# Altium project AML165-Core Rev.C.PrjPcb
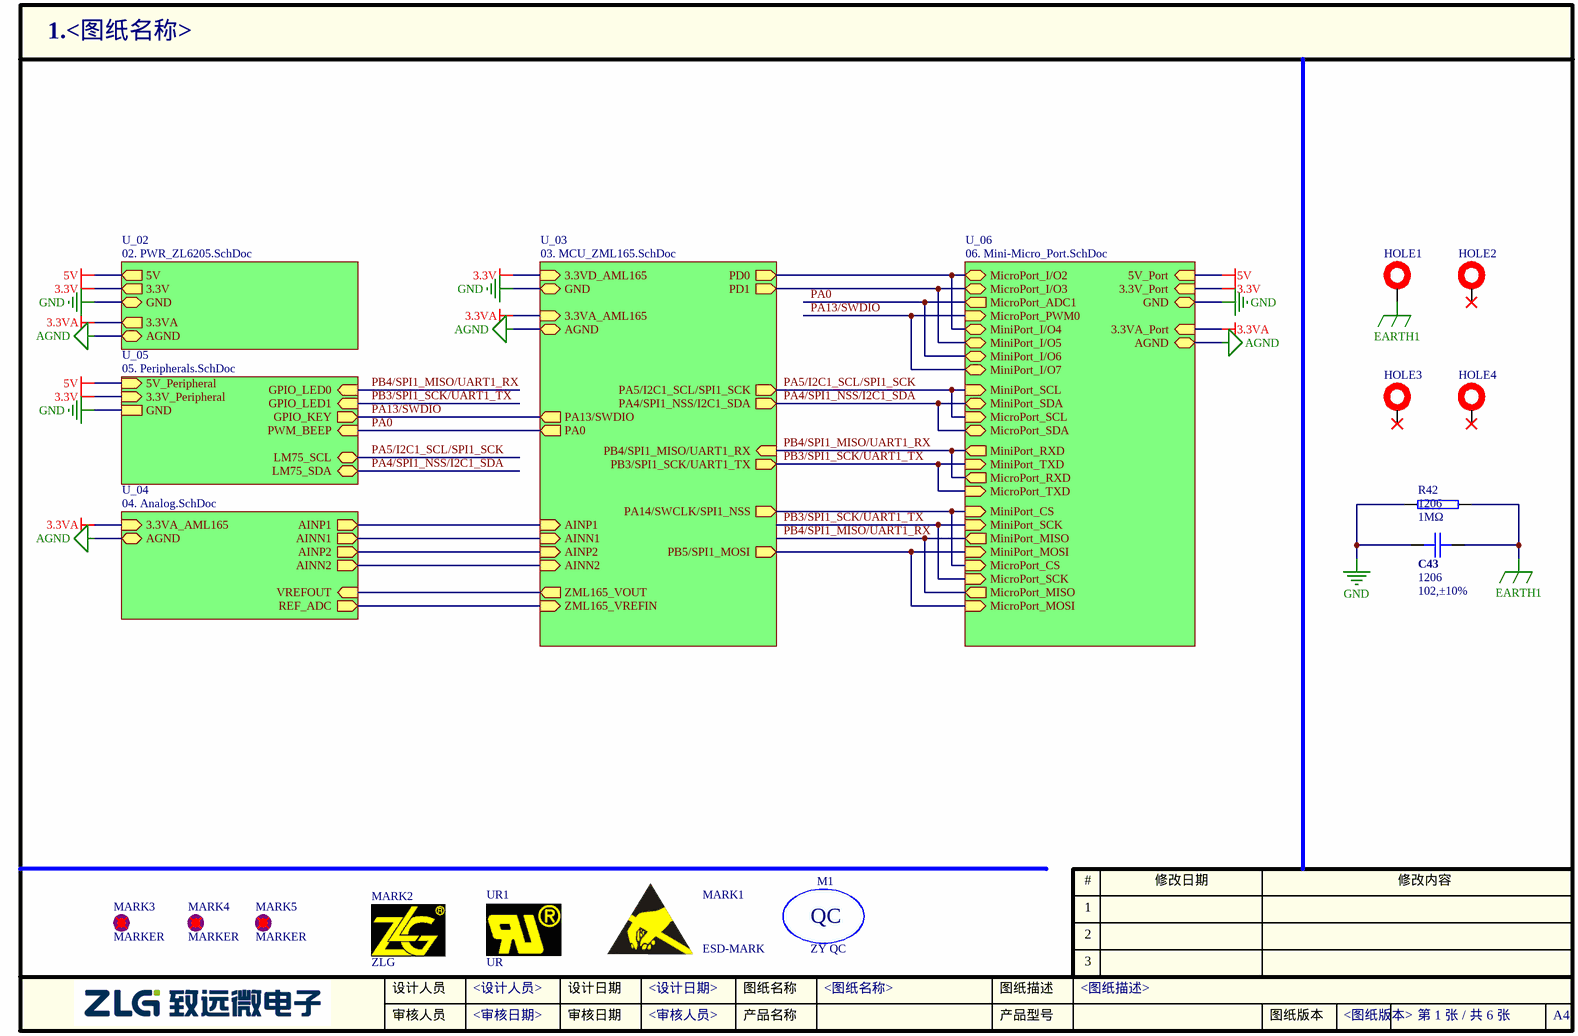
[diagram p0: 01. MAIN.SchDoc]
6 sheets, 150 parts. Net scope: hierarchical (ports join the sheet entries above them; power ports are global).
Board file: AML165-Core Rev.C.PcbDoc
Sheets:
  01. MAIN.SchDoc
    U_04 = 04. Analog.SchDoc
    U_02 = 02. PWR_ZL6205.SchDoc
    U_05 = 05. Peripherals.SchDoc
    U_06 = 06. Mini-Micro_Port.SchDoc
    U_03 = 03. MCU_ZML165.SchDoc

## Sheet 01. MAIN.SchDoc
size A4; CheckedBy: <审核日期>; Author: <设计人员>; CompanyName: 广州立功科技股份有限公司; DocumentNumber: 1; SheetNumber: 1; SheetTotal: 6; PageSetup: Record=PageOptions|CenterHorizontal=True|CenterVertical=True|PrintScale=1.00|XCorrection=1.00|YCorrection=1.00|PrintKind=0|BorderSize=5000000|LeftOffset=0|BottomOffset=0|Orientation=2|PaperLength=1000|PaperWidth=1000|Scale=100|PaperSource=7|PrintQuality=600|MediaType=1|DitherType=10|PaperKind=A4|PrintScaleMode=1; DesignDate: <设计日期>; CheckDate: <审核人员>; SheetName: <图纸名称>; SheetVersion: <图纸版本>; SheetDescription: <图纸描述>

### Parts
C43  封装: 1206  [1206C]  (hidden comment: 102,±10%)
HOLE1  (no value)  [HOLE-3.2]  (no BOM)
HOLE2  (no value)  [HOLE-3.2]  (no BOM)
HOLE3  (no value)  [HOLE-3.2]  (no BOM)
HOLE4  (no value)  [HOLE-3.2]  (no BOM)
M1  ZY QC  [ZY_QC]  (no BOM)
MARK1  ESD-MARK  [ZY_ESD-7]
MARK2  ZLG  [ZLG0.7]  (no BOM)
MARK3  MARKER  [MARKER-C-0.8M]  (no BOM)
MARK4  MARKER  [MARKER-C-0.8M]  (no BOM)
MARK5  MARKER  [MARKER-C-0.8M]  (no BOM)
R42  封装: 1206  [1206R]  (hidden comment: 1MΩ)
UR1  UR  [ZY_UR-3X2]

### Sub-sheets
U_02 = 02. PWR_ZL6205.SchDoc: 5V (out), 3.3V (out), 3.3VA (out), GND (bidir), AGND (bidir)
U_03 = 03. MCU_ZML165.SchDoc: 3.3VD_AML165 (in), GND (bidir), 3.3VA_AML165 (in), AGND (bidir), AINP1 (in), AINN1 (in), AINP2 (in), AINN2 (in), ZML165_VREFIN (in), ZML165_VOUT (out), PB3/SPI1_SCK/UART1_TX (out), PB4/SPI1_MISO/UART1_RX (in), PB5/SPI1_MOSI (out), PA14/SWCLK/SPI1_NSS (out), PA5/I2C1_SCL/SPI1_SCK (out), PA4/SPI1_NSS/I2C1_SDA (out), PA13/SWDIO (out), PA0 (out), PD0 (out), PD1 (out)
U_04 = 04. Analog.SchDoc: 3.3VA_AML165 (in), AGND (bidir), AINP1 (out), AINN1 (out), AINP2 (out), AINN2 (out), REF_ADC (out), VREFOUT (in)
U_05 = 05. Peripherals.SchDoc: GPIO_LED0 (in), GPIO_LED1 (in), PWM_BEEP (in), GPIO_KEY (out), LM75_SCL (bidir), LM75_SDA (bidir), 5V_Peripheral (in), 3.3V_Peripheral (in), GND
U_06 = 06. Mini-Micro_Port.SchDoc: MiniPort_SDA (bidir), MiniPort_SCL (in), MiniPort_MOSI (in), MiniPort_SCK (in), MiniPort_MISO (out), MiniPort_CS (in), MiniPort_TXD (in), MiniPort_RXD (out), MicroPort_RXD (out), MicroPort_TXD (in), MicroPort_SCK (in), MicroPort_MISO (out), MicroPort_MOSI (in), MicroPort_CS (in), MicroPort_SDA (bidir), MicroPort_SCL (in), 3.3V_Port (in), GND (bidir), 3.3VA_Port (in), AGND (bidir), 5V_Port (in), MicroPort_ADC1 (out), MicroPort_PWM0 (in), MiniPort_I/O7 (bidir), MiniPort_I/O6 (bidir), MiniPort_I/O5 (bidir), MiniPort_I/O4 (bidir), MicroPort_I/O2 (bidir), MicroPort_I/O3 (bidir)

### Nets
3.3V: sheet U_02/3.3V, sheet U_05/3.3V_Peripheral, sheet U_06/3.3V_Port, sheet U_03/3.3VD_AML165
3.3VA: sheet U_04/3.3VA_AML165, sheet U_02/3.3VA, sheet U_06/3.3VA_Port, sheet U_03/3.3VA_AML165
5V: sheet U_02/5V, sheet U_05/5V_Peripheral, sheet U_06/5V_Port
AGND: sheet U_04/AGND, sheet U_02/AGND, sheet U_06/AGND, sheet U_03/AGND
EARTH1: C43.2 HOLE1.1 R42.2
GND: C43.1 R42.1 ; sheet U_02/GND, sheet U_05/GND, sheet U_06/GND, sheet U_03/GND
AINN1: sheet U_04/AINN1, sheet U_03/AINN1
AINN2: sheet U_04/AINN2, sheet U_03/AINN2
AINP1: sheet U_04/AINP1, sheet U_03/AINP1
AINP2: sheet U_04/AINP2, sheet U_03/AINP2
MicroPort_CS: sheet U_06/MiniPort_CS, sheet U_06/MicroPort_CS, sheet U_03/PA14/SWCLK/SPI1_NSS
MicroPort_I/O2: sheet U_06/MiniPort_I/O4, sheet U_06/MicroPort_I/O2, sheet U_03/PD0
MicroPort_I/O3: sheet U_06/MiniPort_I/O5, sheet U_06/MicroPort_I/O3, sheet U_03/PD1
MicroPort_MOSI: sheet U_06/MiniPort_MOSI, sheet U_06/MicroPort_MOSI, sheet U_03/PB5/SPI1_MOSI
PA0: sheet U_05/PWM_BEEP, sheet U_06/MicroPort_ADC1, sheet U_06/MiniPort_I/O6, sheet U_03/PA0  [project net MicroPort_ADC1]
PA4/SPI1_NSS/I2C1_SDA: sheet U_05/LM75_SDA, sheet U_06/MiniPort_SDA, sheet U_06/MicroPort_SDA, sheet U_03/PA4/SPI1_NSS/I2C1_SDA  [project net LM75_SDA]
PA5/I2C1_SCL/SPI1_SCK: sheet U_05/LM75_SCL, sheet U_06/MiniPort_SCL, sheet U_06/MicroPort_SCL, sheet U_03/PA5/I2C1_SCL/SPI1_SCK  [project net LM75_SCL]
PA13/SWDIO: sheet U_05/GPIO_KEY, sheet U_06/MicroPort_PWM0, sheet U_06/MiniPort_I/O7, sheet U_03/PA13/SWDIO  [project net GPIO_KEY]
PB3/SPI1_SCK/UART1_TX: sheet U_05/GPIO_LED1, sheet U_06/MiniPort_SCK, sheet U_06/MiniPort_TXD, sheet U_06/MicroPort_TXD, sheet U_06/MicroPort_SCK, sheet U_03/PB3/SPI1_SCK/UART1_TX  [project net GPIO_LED1]
PB4/SPI1_MISO/UART1_RX: sheet U_05/GPIO_LED0, sheet U_06/MiniPort_MISO, sheet U_06/MiniPort_RXD, sheet U_06/MicroPort_RXD, sheet U_06/MicroPort_MISO, sheet U_03/PB4/SPI1_MISO/UART1_RX  [project net GPIO_LED0]
REF_ADC: sheet U_04/REF_ADC, sheet U_03/ZML165_VREFIN
VREFOUT: sheet U_04/VREFOUT, sheet U_03/ZML165_VOUT

Not connected (* = marked no-connect by the designer): HOLE2 1*; HOLE3 1*; HOLE4 1*; MARK3 0*; MARK4 0*; MARK5 0*

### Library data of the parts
C43 = 1.02.03.0003: 102,±10%,2KV,X7R,1206,*,RoHS; 名称: 电容; 设备封装名称: C1206_102_X7R_2KV_10%; 贴片和直插: SMT
HOLE1-HOLE4 = HOLE - 不上螺丝
R42 = 1.01.03.0019: 名称: 电阻; 规格型号: 1MΩ,1206,RoHS; 设备封装名称: R1206_1M; 贴片和直插: SMT; 现有库存: 12252

## Sheet 04. Analog.SchDoc
size A4; CheckedBy: <审核日期>; Author: <设计人员>; CompanyName: 广州立功科技股份有限公司; DocumentNumber: 4; SheetNumber: 4; SheetTotal: 6; PageSetup: Record=PageOptions|CenterHorizontal=True|CenterVertical=True|PrintScale=1.00|XCorrection=1.00|YCorrection=1.00|PrintKind=0|BorderSize=5000000|LeftOffset=0|BottomOffset=0|Orientation=2|PaperLength=1000|PaperWidth=1000|Scale=100|PaperSource=7|PrintQuality=600|MediaType=1|DitherType=10|PaperKind=A4|PrintScaleMode=1; DesignDate: <设计日期>; CheckDate: <审核人员>; SheetName: <图纸名称>; SheetVersion: <图纸版本>; SheetDescription: <图纸描述>
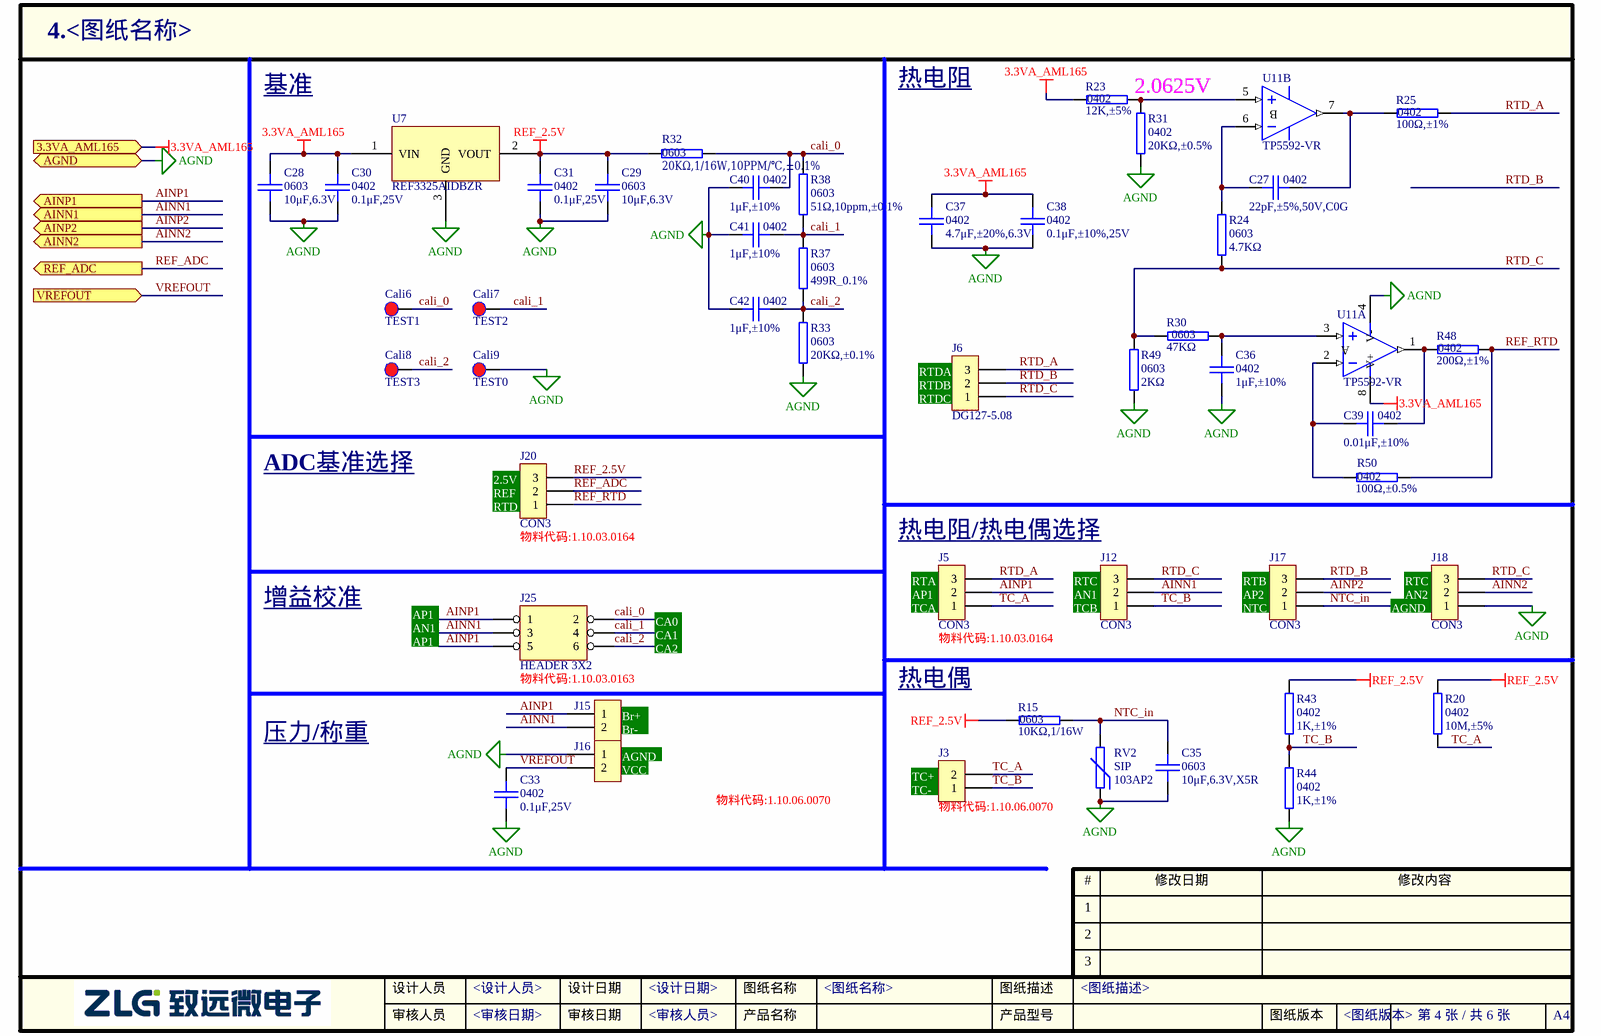
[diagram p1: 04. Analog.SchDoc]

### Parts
C27  封装: 0402  型号: 22pF,±5%,50V,C0G  [0402C]  (hidden comment: 22pF,±5%)
C28  封装: 0603  [0603C]  (hidden comment: 10μF,6.3V)
C29  封装: 0603  [0603C]  (hidden comment: 10μF,6.3V)
C30  封装: 0402  型号: 0.1μF,25V  [0402C]  (hidden comment: GCM155R71E104KE02D,0.1μF)
C31  封装: 0402  型号: 0.1μF,25V  [0402C]  (hidden comment: GCM155R71E104KE02D,0.1μF)
C33  封装: 0402  型号: 0.1μF,25V  [0402C]  (hidden comment: GCM155R71E104KE02D,0.1μF)
C35  封装: 0603  型号: 10μF,6.3V,X5R  [0603C]  (hidden comment: 10μF)
C36  封装: 0402  [0402C]  (hidden comment: 1μF,±10%)
C37  封装: 0402  型号: 4.7μF,±20%,6.3V  [0402C]  (hidden comment: 4.7μF)
C38  封装: 0402  型号: 0.1μF,±10%,25V  [0402C]  (hidden comment: 0.1μF)
C39  封装: 0402  [0402C]  (hidden comment: 0.01μF,±10%)
C40  封装: 0402  [0402C]  (hidden comment: 1μF,±10%)
C41  封装: 0402  [0402C]  (hidden comment: 1μF,±10%)
C42  封装: 0402  [0402C]  (hidden comment: 1μF,±10%)
Cali6  TEST1  [PAD-25/40]  (no BOM)
Cali7  TEST2  [PAD-25/40]  (no BOM)
Cali8  TEST3  [PAD-25/40]  (no BOM)
Cali9  TEST0  [PAD-25/40]  (no BOM)
J3  DG127-5.08-02P-14-00AH,180°  [CON508P1016L810W110D15S-2DIP]  (value not drawn)
J5  CON3  [SIP-3-2.54]
J6  DG127-5.08  [CON508P1524L810W110D15S-3DIP]
J12  CON3  [SIP-3-2.54]
J15  DG127-5.08-02P-14-00AH,180°  [CON508P1016L810W110D15S-2DIP]  (value not drawn)
J16  DG127-5.08-02P-14-00AH,180°  [CON508P1016L810W110D15S-2DIP]  (value not drawn)
J17  CON3  [SIP-3-2.54]
J18  CON3  [SIP-3-2.54]
J20  CON3  [SIP-3-2.54]
J25  HEADER 3X2  [IDC-6-2.54]
R15  封装: 0603  [0603R]  (hidden comment: 10KΩ,1/16W)
R20  封装: 0402  [0402R]  (hidden comment: 10M,±5%)
R23  封装: 0402  [0402R]  (hidden comment: 12K,±5%)
R24  封装: 0603  [0603R]  (hidden comment: 4.7KΩ)
R25  封装: 0402  [0402R]  (hidden comment: 100Ω,±1%)
R30  封装: 0603  [0603R]  (hidden comment: 47KΩ)
R31  封装: 0402  [0402R]  (hidden comment: 20KΩ,±0.5%)
R32  封装: 0603  型号: 20KΩ,1/16W,10PPM/℃,±0.1%  [0603R]  (hidden comment: 20KΩ,1/16W)
R33  封装: 0603  型号: 20KΩ,±0.1%  [0603R]  (hidden comment: 20KΩ,1/16W)
R37  封装: 0603  设备封装名称: 499R_0.1%  [0603R]  (hidden comment: 499Ω)
R38  封装: 0603  型号: 51Ω,10ppm,±0.1%  [0603R]  (hidden comment: 51Ω,10ppm)
R43  封装: 0402  [0402R]  (hidden comment: 1K,±1%)
R44  封装: 0402  [0402R]  (hidden comment: 1K,±1%)
R48  封装: 0402  [0402R]  (hidden comment: 200Ω,±1%)
R49  封装: 0603  [0603R]  (hidden comment: 2KΩ)
R50  封装: 0402  [0402R]  (hidden comment: 100Ω,±0.5%)
RV2  封装: SIP  [RESRR254W35L380T260H850P]  (hidden comment: 103AP2)
U7  REF3325AIDBZR  [SOT-23]
U11  TP5592-VR  [SOP65P490X120-8N]  (parts A,B of 2)

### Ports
3.3VA_AML165 (in), AGND (bidir), AINN1 (out), AINN2 (out), AINP1 (out), AINP2 (out), REF_ADC (out), VREFOUT (in)

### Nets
3.3VA_AML165: C28.2 C30.2 C37.1 C38.1 R23.1 U7.1(VIN) U11.8(V+) ; port 3.3VA_AML165  [project net 3.3VA]
AGND: C28.1 C29.1 C30.1 C31.1 C33.1 C35.1 C36.2 C37.2 C38.2 C40.1 C41.1 C42.1 Cali9.1 J16.1 J18.1 R31.1 R33.2 R44.2 R49.2 RV2.1 U7.3(GND) U11.4(V-) ; port AGND
REF_2.5V: C29.2 C31.2 J20.3 R15.2 R20.1 R32.2 R43.2 U7.2(VOUT)
AINN1: J12.2 J15.2 J25.3 ; port AINN1
AINN2: J18.2 ; port AINN2
AINP1: J5.2 J15.1 J25.1 J25.5 ; port AINP1
AINP2: J17.2 ; port AINP2
cali_0: C40.2 Cali6.1 J25.2 R32.1 R38.1
cali_1: C41.2 Cali7.1 J25.4 R37.2 R38.2
cali_2: C42.2 Cali8.1 J25.6 R33.1 R37.1
NTC_in: C35.2 J17.1 R15.1 RV2.2
REF_ADC: J20.2 ; port REF_ADC
REF_RTD: J20.1 R48.2 R50.1
RTD_A: J5.3 J6.3 R25.1
RTD_B: J6.2 J17.3
RTD_C: J6.1 J12.3 J18.3 R24.2 R30.1 R49.1
TC_A: J3.2 J5.1 R20.2
TC_B: J3.1 J12.1 R43.1 R44.1
VREFOUT: C33.2 J16.2 ; port VREFOUT
NetC27_1: C27.1 R24.1 U11.6(IN-)
NetC27_2: C27.2 R25.2 U11.7(OUT)
NetC36_1: C36.1 R30.2 U11.3(IN+)
NetC39_1: C39.1 R50.2 U11.2(IN-)
NetC39_2: C39.2 R48.1 U11.1(OUT)
NetR23_2: R23.2 R31.2 U11.5(IN+)

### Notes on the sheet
- 基准
- 热电阻
- 2.0625V
- (near J6) RTDA
  RTDB
  RTDC
- ADC基准选择
- (near J20) 2.5V
- (near J20) REF
- (near J20) RTD
- (near J20) 物料代码:1.10.03.0164
- (near J5) 热电阻/热电偶选择
- (near J5) RTA
- (near J12) RTC
- (near J17) RTB
- (near J18) RTC
- 增益校准
- AP1
- AN1
- CA0
- CA1
- CA2
- (near J5) TCA
- (near J5) AP1
- (near J5) 物料代码:1.10.03.0164
- (near J12) TCB
- (near J12) AN1
- (near J17) NTC
- (near J17) AP2
- (near J18) AGND
- (near J18) AN2
- 物料代码:1.10.03.0163
- Br+
- 热电偶
- 压力/称重
- Br-
- VCC
- AGND
- (near J3) TC+
- (near J3) TC-
- (near J16) 物料代码:1.10.06.0070
- (near J3) 物料代码:1.10.06.0070

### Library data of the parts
C27 = 1.02.17.0036: GRM1555C1H220JA01D,22pF,±5%,50V,C0G,0402,muRata,RoHS; 名称: 电容; 设备封装名称: C0402_22PF_NPO_50V_5%; 贴片和直插: SMT; 器件优选方案: 正常状态，可以选用
C28 C29 C35 = 1.02.01.0065: 10μF,6.3V,X5R,GRM188R60J106M****,0603,Murata,RoHS; 名称: 电容; 贴片和直插: SMT; 器件优选方案: 正常状态，可以选用
C30 C31 C33 C38 = 1.02.17.0118: GCM155R71E104KE02D,0.1μF,±10%,25V,X7R,0402,muRata,RoHS; 名称: 电容; 贴片和直插: SMT; PCB备注: 161012yjh; 器件优选方案: 正常状态，可以选用
C36 C40-C42 = 1.02.17.0092: GRM155R61C105KA12D,1μF,±10% ,16V,X5R,0402,muRata,RoHS; 名称: 电容; 贴片和直插: SMT; PCB备注: 无数据手册，依据采购部提供的信息添加的封装。; 器件优选方案: 正常状态，可以选用
C37 = 1.02.17.0073: GRM155R60J475ME87D,4.7μF,±20%,6.3V,X5R,0402,muRata,RoHS; 名称: 电容; 贴片和直插: SMT; 器件优选方案: 正常状态，可以选用
C39 = 1.02.17.0019: GRM155R71H103KA88D,0.01μF,±10%,50V,X7R,0402,muRata,RoHS; 名称: 电容; 设备封装名称: C0402_0.01uF_X7R_50V_10%; 贴片和直插: SMT; 器件优选方案: 正常状态，可以选用
Cali6-Cali9 = TEST-DOT
J3 J15 J16 = 1.10.06.0070: DG127-5.08-02P-14-00AH,180°,绿色,DEGSON,RoHS; 名称: 端子; 贴片和直插: THT; PCB备注: xhm-lq-wyy-150126 yyf改名称180925; 器件优选方案: 正常状态，可以选用
J5 J12 J17 J18 J20 = CON3: Connector
J6 = 19.04.00251: DG127-5.08-03P-14-00AH,180°,绿色,THT; 名称: 端子; PCB备注: 180925 yyf
R15 = 1.01.01.0192: 10KΩ,1/16W,10PPM/℃,±0.1%,0603,Viking,RoHS; 名称: 电阻; 设备封装名称: R0603_10K_0.1%; 型号: 10KΩ,±0.1%; 贴片和直插: SMT; 器件优选方案: 临时/偏门物料/不主推物料，谨慎选用
R20 = 1.01.17.0005: 10M,±5%,0402,RALEC,RoHS; 名称: 电阻; 设备封装名称: R0402_10M; 贴片和直插: SMT; 器件优选方案: 正常状态，可以选用
R23 = 1.01.17.0035: 12K,±5%,0402,RALEC,RoHS; 名称: 电阻; 设备封装名称: R0402_12K; 贴片和直插: SMT; 器件优选方案: 正常状态，可以选用
R24 = 1.01.01.0045: 4.7KΩ,0603,*,RoHS; 名称: 电阻; 设备封装名称: R0603_4.7K; 厂商: Ralec; 贴片和直插: SMT; 器件优选方案: 正常状态，可以选用
R25 = 1.01.17.0029: 100Ω,±1%,0402,RALEC,RoHS; 名称: 电阻; 设备封装名称: R0402_100R_1%; 贴片和直插: SMT; 器件优选方案: 正常状态，可以选用
R30 = 1.01.01.0060: 47KΩ,0603,*,RoHS; 名称: 电阻; 设备封装名称: R0603_47K; 厂商: Ralec; 贴片和直插: SMT; 器件优选方案: 正常状态，可以选用
R31 = 1.01.17.0053: 20KΩ,±0.5%,0402,RoHS; 名称: 电阻; 设备封装名称: R0402_20K_0.5%; 厂商: Ralec; 贴片和直插: SMT; 器件优选方案: 正常状态，可以选用
R32 R33 = 1.01.01.0207: 20KΩ,1/16W,10PPM/℃,±0.1%,0603,Viking,RoHS; 名称: 电阻; 贴片和直插: SMT; 器件优选方案: 临时/偏门物料/不主推物料，谨慎选用
R37 = 1.01.01.0155: 499Ω,RN731JTTD,4990B10,0603,KOA,RoHS; 名称: 电阻; 贴片和直插: SMT; 器件优选方案: 临时/偏门物料/不主推物料，谨慎选用
R38 = 1.01.01.0215: 51Ω,10ppm,±0.1%,AR03BTB0510,0603,Viking,RoHS; 名称: 电阻; 贴片和直插: SMT; 器件优选方案: 临时/偏门物料/不主推物料，谨慎选用
R43 R44 = 1.01.17.0016: 1K,±1%,0402,RALEC,RoHS; 名称: 电阻; 设备封装名称: R0402_1K_1%; 贴片和直插: SMT; 器件优选方案: 正常状态，可以选用
R48 = 1.01.17.0073: 200Ω,±1%,0402,RoHS; 名称: 电阻; 设备封装名称: R0402_200R_1%; 厂商: Ralec; 贴片和直插: SMT; 器件优选方案: 正常状态，可以选用
R49 = 1.01.01.0157: 2KΩ,RN731JTTD,2001B10,0603,KOA,RoHS; 名称: 电阻; 设备封装名称: R0603_2K_0.1%; 贴片和直插: SMT; 器件优选方案: 临时/偏门物料/不主推物料，谨慎选用
R50 = 1.01.17.0052: 100Ω,±0.5%,0402,RoHS; 名称: 电阻; 设备封装名称: R0402_100R_0.5%; 厂商: Ralec; 贴片和直插: SMT; 器件优选方案: 正常状态，可以选用
RV2 = 1.01.14.0020: 103AP2,SIP,semitec,RoHS; 名称: 热敏电阻(临时); 贴片和直插: THT; PCB备注: 171205CZY; 器件优选方案: 临时/偏门物料/不主推物料，谨慎选用
U7 = 1.05.10.0334: REF3325AIDBZR,SOT-23,TI; 名称: 集成电路; 设备封装名称: SOT-23_REF3325AIDBZR; 贴片和直插: SMT; 器件优选方案: 量产物料,优先选用
U11 = 1.05.20.0102: TP5592-VR,MSOP-8,3PEAK,RoHS; 名称: 集成电路(临时); 贴片和直插: SMT; PCB备注: 170810lmd; 器件优选方案: 临时/偏门物料/不主推物料，谨慎选用

## Sheet 02. PWR_ZL6205.SchDoc
size A4; CheckedBy: <审核日期>; Author: <设计人员>; CompanyName: 广州立功科技股份有限公司; DocumentNumber: 2; SheetNumber: 2; SheetTotal: 6; PageSetup: Record=PageOptions|CenterHorizontal=True|CenterVertical=True|PrintScale=1.00|XCorrection=1.00|YCorrection=1.00|PrintKind=0|BorderSize=5000000|LeftOffset=0|BottomOffset=0|Orientation=2|PaperLength=1000|PaperWidth=1000|Scale=100|PaperSource=7|PrintQuality=600|MediaType=1|DitherType=10|PaperKind=A4|PrintScaleMode=1; DesignDate: <设计日期>; CheckDate: <审核人员>; SheetName: <图纸名称>; SheetVersion: <图纸版本>; SheetDescription: <图纸描述>
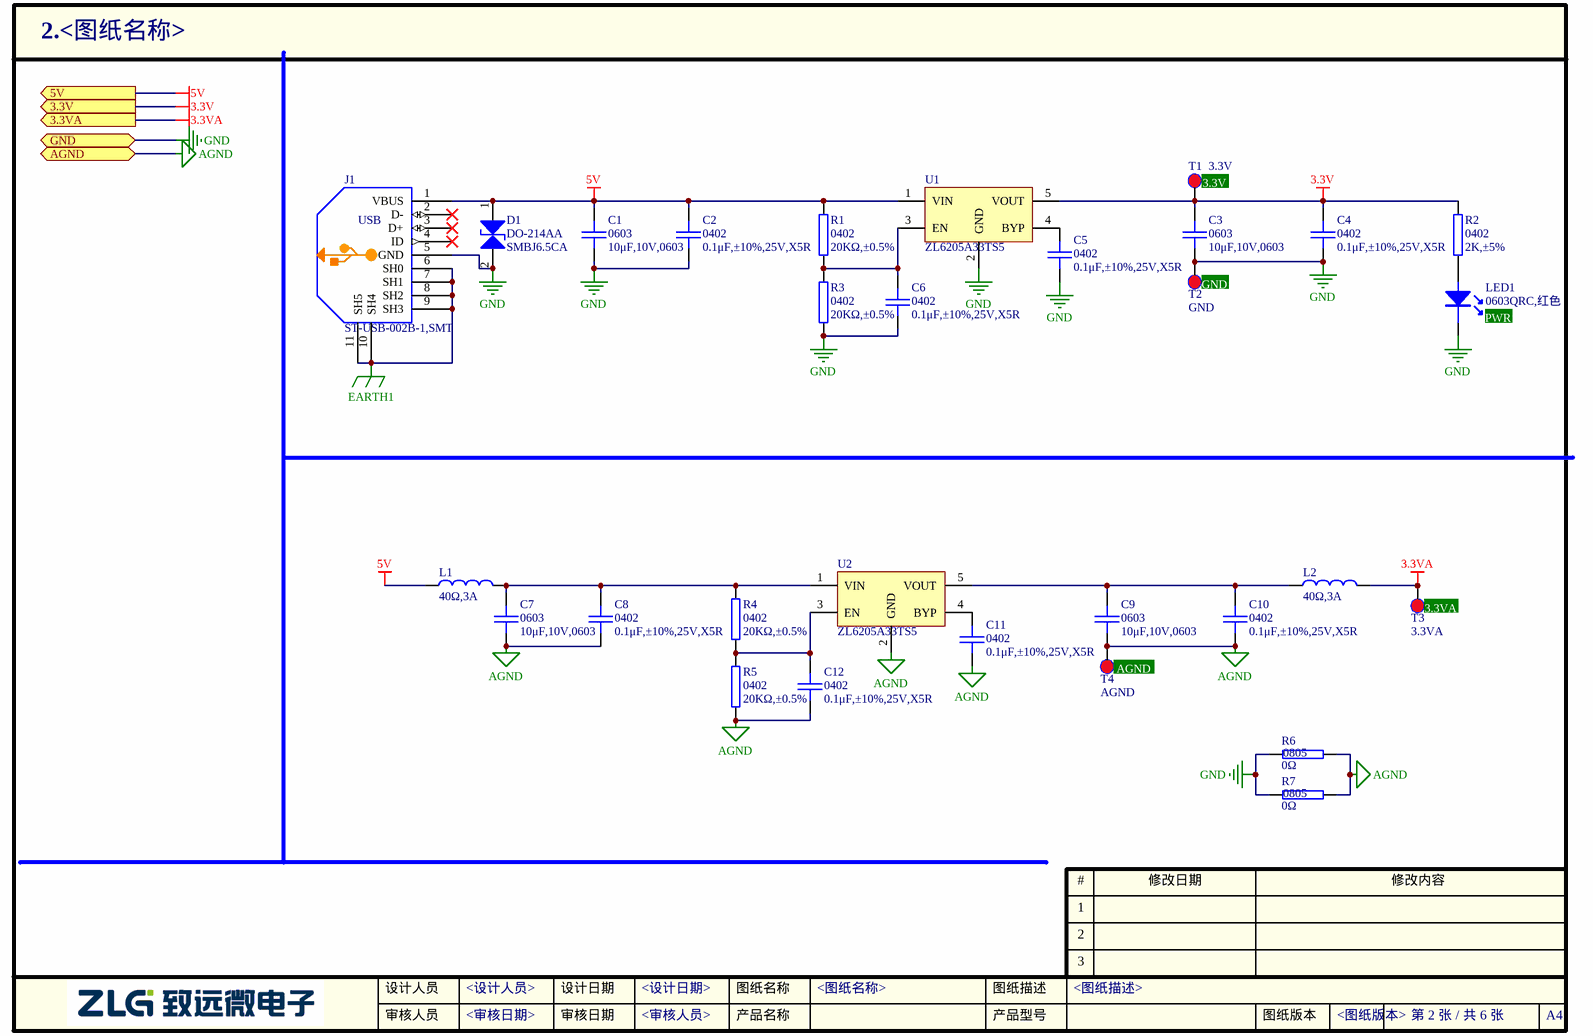
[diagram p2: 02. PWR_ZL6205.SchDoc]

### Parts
C1  封装: 0603  [0603C]  (hidden comment: 10μF,10V,0603)
C2  封装: 0402  型号: 0.1μF,±10%,25V,X5R  [0402C]  (hidden comment: 0.1μF,±10%)
C3  封装: 0603  [0603C]  (hidden comment: 10μF,10V,0603)
C4  封装: 0402  型号: 0.1μF,±10%,25V,X5R  [0402C]  (hidden comment: 0.1μF,±10%)
C5  封装: 0402  型号: 0.1μF,±10%,25V,X5R  [0402C]  (hidden comment: 0.1μF,±10%)
C6  封装: 0402  型号: 0.1μF,±10%,25V,X5R  [0402C]  (hidden comment: 0.1μF,±10%)
C7  封装: 0603  [0603C]  (hidden comment: 10μF,10V,0603)
C8  封装: 0402  型号: 0.1μF,±10%,25V,X5R  [0402C]  (hidden comment: 0.1μF,±10%)
C9  封装: 0603  [0603C]  (hidden comment: 10μF,10V,0603)
C10  封装: 0402  型号: 0.1μF,±10%,25V,X5R  [0402C]  (hidden comment: 0.1μF,±10%)
C11  封装: 0402  型号: 0.1μF,±10%,25V,X5R  [0402C]  (hidden comment: 0.1μF,±10%)
C12  封装: 0402  型号: 0.1μF,±10%,25V,X5R  [0402C]  (hidden comment: 0.1μF,±10%)
D1  封装: DO-214AA  [SOD-1812]  (hidden comment: SMBJ6.5CA)
J1  ST-USB-002B-1,SMT  [MICROUSB-ST-USB-002B-1]
L1  40Ω,3A  [0603L]
L2  40Ω,3A  [0603L]
LED1  0603QRC,红色  [LED-0603]
R1  封装: 0402  [0402R]  (hidden comment: 20KΩ,±0.5%)
R2  封装: 0402  [0402R]  (hidden comment: 2K,±5%)
R3  封装: 0402  [0402R]  (hidden comment: 20KΩ,±0.5%)
R4  封装: 0402  [0402R]  (hidden comment: 20KΩ,±0.5%)
R5  封装: 0402  [0402R]  (hidden comment: 20KΩ,±0.5%)
R6  封装: 0805  [0805R]  (hidden comment: 0Ω)
R7  封装: 0805  [0805R]  (hidden comment: 0Ω)
T1  3.3V  [PAD-25/40]  (no BOM)
T2  GND  [PAD-25/40]  (no BOM)
T3  3.3VA  [PAD-25/40]  (no BOM)
T4  AGND  [PAD-25/40]  (no BOM)
U1  ZL6205A33TS5  [SOT-23-5]
U2  ZL6205A33TS5  [SOT-23-5]

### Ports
3.3V (out), 3.3VA (out), 5V (out), AGND (bidir), GND (bidir)

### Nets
3.3V: C3.1 C4.2 R2.2 T1.1 U1.5(VOUT) ; port 3.3V
3.3VA: L2.2 T3.1 ; port 3.3VA
5V: C1.1 C2.2 D1.1(A) J1.1(VBUS) L1.1 R1.1 U1.1(VIN) ; port 5V
AGND: C7.2 C8.1 C9.2 C10.1 C11.1 C12.1 R5.2 R6.2 R7.2 T4.1 U2.2(GND) ; port AGND
EARTH1: J1.6(SH0) J1.7(SH1) J1.8(SH2) J1.9(SH3) J1.10(SH4) J1.11(SH5)
GND: C1.2 C2.1 C3.2 C4.1 C5.1 C6.1 D1.2(K) J1.5(GND) LED1.2 R3.2 R6.1 R7.1 T2.1 U1.2(GND) ; port GND
NetC5_2: C5.2 U1.4(BYP)
NetC6_2: C6.2 R1.2 R3.1 U1.3(EN)
NetC7_1: C7.1 C8.2 L1.2 R4.1 U2.1(VIN)
NetC9_1: C9.1 C10.2 L2.1 U2.5(VOUT)
NetC11_2: C11.2 U2.4(BYP)
NetC12_2: C12.2 R4.2 R5.1 U2.3(EN)
NetLED1_1: LED1.1 R2.1

Not connected (* = marked no-connect by the designer): J1 2(D-)* 3(D+)* 4(ID)*

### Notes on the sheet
- (near T1) 3.3V
- (near T2) GND
- (near LED1) PWR
- (near T3) 3.3VA
- (near T4) AGND

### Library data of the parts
C1 C3 C7 C9 = 02.01.00456: GRM188D71A106MA73D,0603,Murata,10μF,X7T,±20%,10V; 名称: 电容; 贴片和直插: SMT; PCB备注: 190613hcj; 器件优选方案: 通用物料
C2 C4-C6 C8 C10-C12 = 1.02.17.0020: GRM155R61E104KA87D,0.1μF,±10%,25V,X5R,0402,muRata,RoHS; 名称: 电容; 设备封装名称: C0402_0.1uF_X5R_25V_10%; 贴片和直插: SMT; 器件优选方案: 正常状态，可以选用
D1 = 1.04.03.0003: SMBJ6.5CA,DO-214AA,君耀,RoHS; 名称: TVS瞬态抑制二极管; 设备封装名称: DO-214AA_SMBJ6.5CA; 贴片和直插: SMT; 器件优选方案: 正常状态，可以选用
J1 = 20.02.00033: ST-USB-002B-1,SMT,SUNGTECH,MicroUSB-A; 名称: 连接器; PCB备注: 190710lmd; 器件优选方案: 通用物料
L1 L2 = 1.03.03.0011: 40Ω,3A,DCR35mΩ,BH03Y314S-40R,SMD,0603,丰晶,RoHS; 名称: 磁珠; 封装: 0603; 贴片和直插: SMT; 器件优选方案: 正常状态，可以选用
LED1 = 1.04.05.0008: 0603QRC,红色,0603,创光,RoHS; 名称: 发光二极管; 封装: 0603; 设备封装名称: LED0603-RED; 贴片和直插: SMT; 器件优选方案: 正常状态，可以选用
R1 R3-R5 = 1.01.17.0053: as R31 on sheet 04. Analog
R2 = 1.01.17.0032: 2K,±5%,0402,RALEC,RoHS; 名称: 电阻; 设备封装名称: R0402_2K; 贴片和直插: SMT; 器件优选方案: 正常状态，可以选用
R6 R7 = 1.01.02.0001: 0Ω,0805,*,RoHS; 名称: 电阻; 设备封装名称: R0805_0R; 厂商: Ralec; 贴片和直插: SMT; 器件优选方案: 正常状态，可以选用
T1-T4 = TEST-DOT
U1 U2 = 08.09.03069: ZL6205A33TS5,SOT-23-5,ZLG; 名称: 集成电路; 贴片和直插: SMT; PCB备注: 190806hcj; 器件优选方案: 待导入物料

## Sheet 05. Peripherals.SchDoc
size A4; CheckedBy: <审核日期>; Author: <设计人员>; CompanyName: 广州立功科技股份有限公司; DocumentNumber: 5; SheetNumber: 5; SheetTotal: 6; PageSetup: Record=PageOptions|CenterHorizontal=True|CenterVertical=True|PrintScale=1.00|XCorrection=1.00|YCorrection=1.00|PrintKind=0|BorderSize=5000000|LeftOffset=0|BottomOffset=0|Orientation=2|PaperLength=1000|PaperWidth=1000|Scale=100|PaperSource=7|PrintQuality=600|MediaType=1|DitherType=10|PaperKind=A4|PrintScaleMode=1; DesignDate: <设计日期>; CheckDate: <审核人员>; SheetName: <图纸名称>; SheetVersion: <图纸版本>; SheetDescription: <图纸描述>
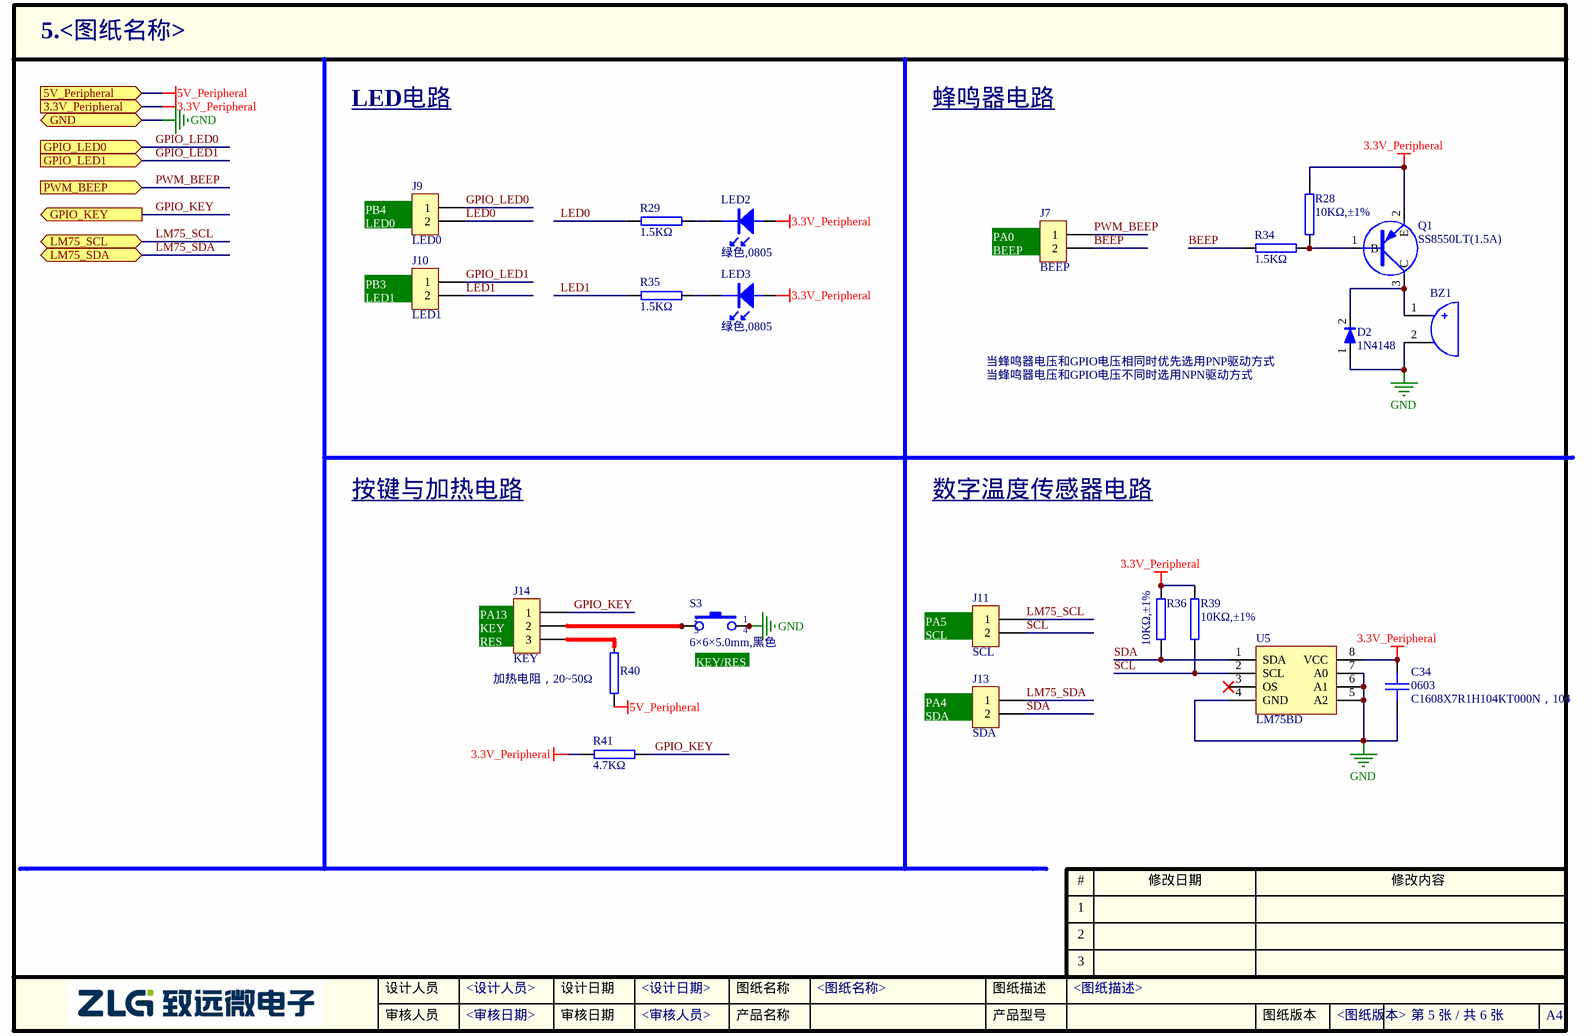
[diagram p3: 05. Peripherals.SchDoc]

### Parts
BZ1  BUZZER2  [BUZZ-4/9]  (value not drawn)
C34  封装: 0603  [0603C]  (hidden comment: C1608X7R1H104KT000N，104)
D2  value 1N4148  [SOD-323]  (hidden comment: DIODE1)
J7  BEEP  [SIP-2-2.54]
J9  LED0  [SIP-2-2.54]
J10  LED1  [SIP-2-2.54]
J11  SCL  [SIP-2-2.54]
J13  SDA  [SIP-2-2.54]
J14  KEY  [SIP-3-2.54]
LED2  value 绿色,0805  [LED-0805]  (hidden comment: LED0)
LED3  value 绿色,0805  [LED-0805]  (hidden comment: LED1)
Q1  value SS8550LT(1.5A)  [SOT-23]  (hidden comment: PNP-1)
R28  10KΩ,±1%  [0603R]
R29  1.5KΩ  [0603R]
R34  1.5KΩ  [0603R]
R35  1.5KΩ  [0603R]
R36  10KΩ,±1%  [0603R]
R39  10KΩ,±1%  [0603R]
R40  20Ω,±5%  [RESAD1778W80L1450D430P]  (value not drawn)
R41  4.7KΩ  [0603R]
S3  value 6×6×5.0mm,黑色  [KEY-6S]  (hidden comment: KEY/RES)
U5  value LM75BD  [SOIC127P600X175-8N]  (hidden comment: LM75B)

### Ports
3.3V_Peripheral (in), 5V_Peripheral (in), GND, GPIO_KEY (out), GPIO_LED0 (in), GPIO_LED1 (in), LM75_SCL (bidir), LM75_SDA (bidir), PWM_BEEP (in)

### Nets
3.3V_Peripheral: C34.1 LED2.1 LED3.1 Q1.2(E) R28.2 R36.2 R39.2 R41.2 U5.8(VCC) ; port 3.3V_Peripheral  [project net 3.3V]
5V_Peripheral: R40.1 ; port 5V_Peripheral  [project net 5V]
GND: BZ1.2(B) C34.2 D2.1 S3.1 S3.4 U5.4(GND) U5.5(A2) U5.6(A1) U5.7(A0) ; port GND
BEEP: J7.2 R34.1
GPIO_KEY: J14.1 R41.1 ; port GPIO_KEY
GPIO_LED0: J9.1 ; port GPIO_LED0
GPIO_LED1: J10.1 ; port GPIO_LED1
LED0: J9.2 R29.2
LED1: J10.2 R35.2
LM75_SCL: J11.1 ; port LM75_SCL
LM75_SDA: J13.1 ; port LM75_SDA
PWM_BEEP: J7.1 ; port PWM_BEEP  [project net MicroPort_ADC1]
SCL: J11.2 R39.1 U5.2(SCL)
SDA: J13.2 R36.1 U5.1(SDA)
NetBZ1_1: BZ1.1(A) D2.2 Q1.3(C)
NetJ14_2: J14.2 S3.2 S3.3
NetJ14_3: J14.3 R40.2
NetLED2_2: LED2.2 R29.1
NetLED3_2: LED3.2 R35.1
NetQ1_1: Q1.1(B) R28.1 R34.2

Not connected (* = marked no-connect by the designer): U5 3(OS)*

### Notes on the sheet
- LED电路
- 蜂鸣器电路
- (near J9) LED0
- (near J9) PB4
- (near J7) PA0
- (near J7) BEEP
- (near J10) LED1
- (near J10) PB3
- 当蜂鸣器电压和GPIO电压不同时选用NPN驱动方式
- 当蜂鸣器电压和GPIO电压相同时优先选用PNP驱动方式
- 按键与加热电路
- 数字温度传感器电路
- (near J14) RES
- (near J14) KEY
- (near J14) PA13
- (near J11) PA5
- (near J11) SCL
- 加热电阻，20~50Ω
- (near S3) KEY/RES
- (near J13) PA4
- (near J13) SDA

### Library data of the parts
BZ1 = 1.06.09.0016: Buzzer有极性; Value: AS-905I-LF,无源; 名称: 讯响器; 厂商: 常州笠翔; 型号: AS-905I-LF,无源,Ф9×4.8mm; 贴片和直插: THT; PCB备注: Flq-Shcj-Twrj-150113; 器件优选方案: 量产物料,优先选用
C34 = 1.02.01.0072: C1608X7R1H104KT000N，104，±10%，50V，X7R,TDK,0603,RoHS; 名称: 电容; 贴片和直插: SMT; PCB备注: 151110lmd; 器件优选方案: 正常状态，可以选用
D2 = 1.04.07.0027: 1N4148,SOD-323,RoHS; 名称: 二极管; 设备封装名称: SOD-323_1N4148; 贴片和直插: SMT
J7 J9-J11 J13 = CON2: Connector; 物料代码: 1.10.03.0164
J14 = CON3: Connector; 物料代码: 1.10.03.0164
LED2 LED3 = 1.04.05.0002: 绿色,0805,0805,RoHS; 名称: 发光二极管; 封装: 0805; 设备封装名称: LED0805-GREEN; 贴片和直插: SMT; 器件优选方案: 样品物料,谨慎选用
Q1 = 1.04.09.0002: PNP Transistor; 名称: 三极管; 设备封装名称: SOT-23_SS8550LT; 厂商: 江苏长电; 贴片和直插: SMT
R28 = 1.01.01.0052: 10KΩ,±1%,0603,*,RoHS; 名称: 电阻; 封装: 0603; 设备封装名称: R0603_10K_1%; 厂商: Ralec; 贴片和直插: SMT
R29 R35 = 1.01.01.0037: 1.5KΩ,0603,*,RoHS; 名称: 电阻; 封装: 0603; 设备封装名称: R0603_1.5K; 厂商: Ralec; 贴片和直插: SMT; 器件优选方案: 正常状态，可以选用
R34 = 1.01.01.0037: 1.5KΩ,0603,*,RoHS; 名称: 电阻; 封装: 0603; 设备封装名称: R0603_1.5K; 厂商: Ralec; 贴片和直插: SMT; 器件优选方案: 状态正常
R36 R39 = 1.01.01.0052: 10KΩ,±1%,0603,*,RoHS; 名称: 电阻; 封装: 0603; 设备封装名称: R0603_10K_1%; 厂商: Ralec; 贴片和直插: SMT; 器件优选方案: 正常状态，可以选用
R40 = 1.01.10.0003: 20Ω,±5%,2W,Ф5.5×16mm,RoHS; 名称: 电阻; 贴片和直插: THT
R41 = 1.01.01.0045: 4.7KΩ,0603,*,RoHS; 名称: 电阻; 封装: 0603; 设备封装名称: R0603_4.7K; 厂商: Ralec; 贴片和直插: SMT; 器件优选方案: 正常状态，可以选用
S3 = 1.09.01.0003: 6×6×5.0mm,黑色,SMD,,*; 名称: 轻触按键; 贴片和直插: SMT
U5 = 1.05.10.0602: LM75BD,SO-9,NXP,RoHS; 名称: IC; 封装: SO-8; 贴片和直插: SMT; 器件优选方案: 样品物料,谨慎选用

## Sheet 06. Mini-Micro_Port.SchDoc
size A4; CheckedBy: <审核日期>; Author: <设计人员>; CompanyName: 广州立功科技股份有限公司; DocumentNumber: 6; SheetNumber: 6; SheetTotal: 6; PageSetup: Record=PageOptions|CenterHorizontal=True|CenterVertical=True|PrintScale=1.00|XCorrection=1.00|YCorrection=1.00|PrintKind=0|BorderSize=5000000|LeftOffset=0|BottomOffset=0|Orientation=2|PaperLength=1000|PaperWidth=1000|Scale=100|PaperSource=7|PrintQuality=600|MediaType=1|DitherType=10|PaperKind=A4|PrintScaleMode=1; DesignDate: <设计日期>; CheckDate: <审核人员>; SheetName: <图纸名称>; SheetVersion: <图纸版本>; SheetDescription: <图纸描述>
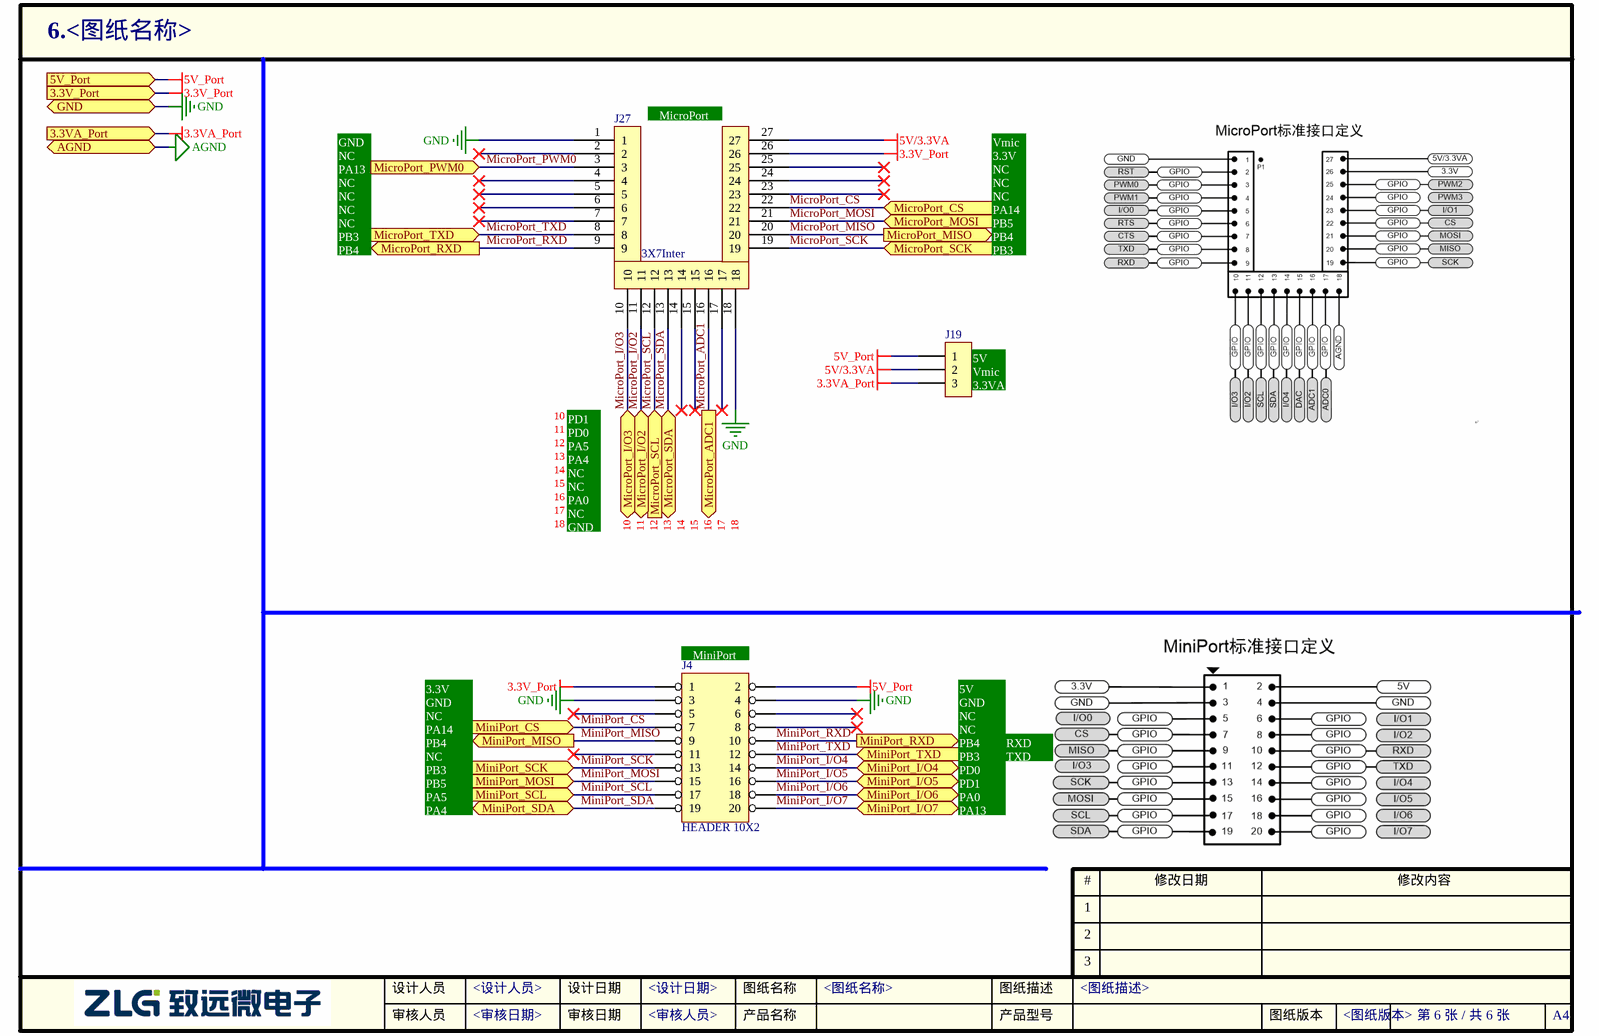
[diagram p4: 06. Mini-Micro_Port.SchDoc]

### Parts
J4  HEADER 10X2  [IDC-20-2.54-R90]
J19  (no value)  [SIP-3-2.54]
J27  3X7Inter  [SIP-27 2.54C]

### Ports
3.3V_Port (in), 3.3VA_Port (in), 5V_Port (in), AGND (bidir), GND (bidir), MicroPort_ADC1 (out), MicroPort_CS (in), MicroPort_I/O2 (bidir), MicroPort_I/O3 (bidir), MicroPort_MISO (out), MicroPort_MOSI (in), MicroPort_PWM0 (in), MicroPort_RXD (out), MicroPort_SCK (in), MicroPort_SCL (in), MicroPort_SDA (bidir), MicroPort_TXD (in), MiniPort_CS (in), MiniPort_I/O4 (bidir), MiniPort_I/O5 (bidir), MiniPort_I/O6 (bidir), MiniPort_I/O7 (bidir), MiniPort_MISO (out), MiniPort_MOSI (in), MiniPort_RXD (out), MiniPort_SCK (in), MiniPort_SCL (in), MiniPort_SDA (bidir), MiniPort_TXD (in)

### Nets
3.3V_Port: J4.1 J27.26 ; port 3.3V_Port  [project net 3.3V]
3.3VA_Port: J19.3 ; port 3.3VA_Port  [project net 3.3VA]
5V/3.3VA: J19.2 J27.27
5V_Port: J4.2 J19.1 ; port 5V_Port  [project net 5V]
GND: J4.3 J4.4 J27.1 J27.18 ; port GND
MicroPort_ADC1: J4.18 J27.16 ; port MicroPort_ADC1, port MiniPort_I/O6  [also labelled MiniPort_I/O6]
MicroPort_CS: J4.7 J27.22 ; port MiniPort_CS, port MicroPort_CS  [also labelled MiniPort_CS]
MicroPort_I/O2: J4.14 J27.11 ; port MiniPort_I/O4, port MicroPort_I/O2  [also labelled MiniPort_I/O4]
MicroPort_I/O3: J4.16 J27.10 ; port MiniPort_I/O5, port MicroPort_I/O3  [also labelled MiniPort_I/O5]
MicroPort_MISO: J4.9 J4.10 J27.9 J27.20 ; port MiniPort_MISO, port MiniPort_RXD, port MicroPort_RXD, port MicroPort_MISO  [also labelled MicroPort_RXD, MiniPort_MISO, MiniPort_RXD]  [project net GPIO_LED0]
MicroPort_MOSI: J4.15 J27.21 ; port MiniPort_MOSI, port MicroPort_MOSI  [also labelled MiniPort_MOSI]
MicroPort_PWM0: J4.20 J27.3 ; port MicroPort_PWM0, port MiniPort_I/O7  [also labelled MiniPort_I/O7]  [project net GPIO_KEY]
MicroPort_SCK: J4.12 J4.13 J27.8 J27.19 ; port MiniPort_SCK, port MiniPort_TXD, port MicroPort_TXD, port MicroPort_SCK  [also labelled MicroPort_TXD, MiniPort_SCK, MiniPort_TXD]  [project net GPIO_LED1]
MicroPort_SCL: J4.17 J27.12 ; port MiniPort_SCL, port MicroPort_SCL  [also labelled MiniPort_SCL]  [project net LM75_SCL]
MicroPort_SDA: J4.19 J27.13 ; port MiniPort_SDA, port MicroPort_SDA  [also labelled MiniPort_SDA]  [project net LM75_SDA]

Not connected (* = marked no-connect by the designer): J4 5* 6* 8* 11*; J27 2* 4* 5* 6* 7* 14* 15* 17* 23* 24* 25*

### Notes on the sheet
- (near J27) MicroPort
- NC
- PA13
- GND
- 3.3V
- Vmic
- PB3
- PB4
- PA14
- PB5
- (near J19) 5V
- (near J19) Vmic
  3.3VA
- 10
- 11
- 12
- PA5
- PD1
- PD0
- 13
- 14
- 15
- 16
- 17
- PA0
- PA4
- 18
- (near J4) MiniPort
- 5V
- RXD
- TXD

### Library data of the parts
J4 = HEADER 10X2: 物料代码: 1.10.03.0016
J19 = CON3: Connector; 物料代码: 1.10.03.0164
J27 = 3X7Inter: 物料代码: 1.10.11.0074

## Sheet 03. MCU_ZML165.SchDoc
size A4; CheckedBy: <审核日期>; Author: <设计人员>; CompanyName: 广州立功科技股份有限公司; DocumentNumber: 3; SheetNumber: 3; SheetTotal: 6; PageSetup: Record=PageOptions|CenterHorizontal=True|CenterVertical=True|PrintScale=1.00|XCorrection=1.00|YCorrection=1.00|PrintKind=0|BorderSize=5000000|LeftOffset=0|BottomOffset=0|Orientation=2|PaperLength=1000|PaperWidth=1000|Scale=100|PaperSource=7|PrintQuality=600|MediaType=1|DitherType=10|PaperKind=A4|PrintScaleMode=1; DesignDate: <设计日期>; CheckDate: <审核人员>; SheetName: <图纸名称>; SheetVersion: <图纸版本>; SheetDescription: <图纸描述>
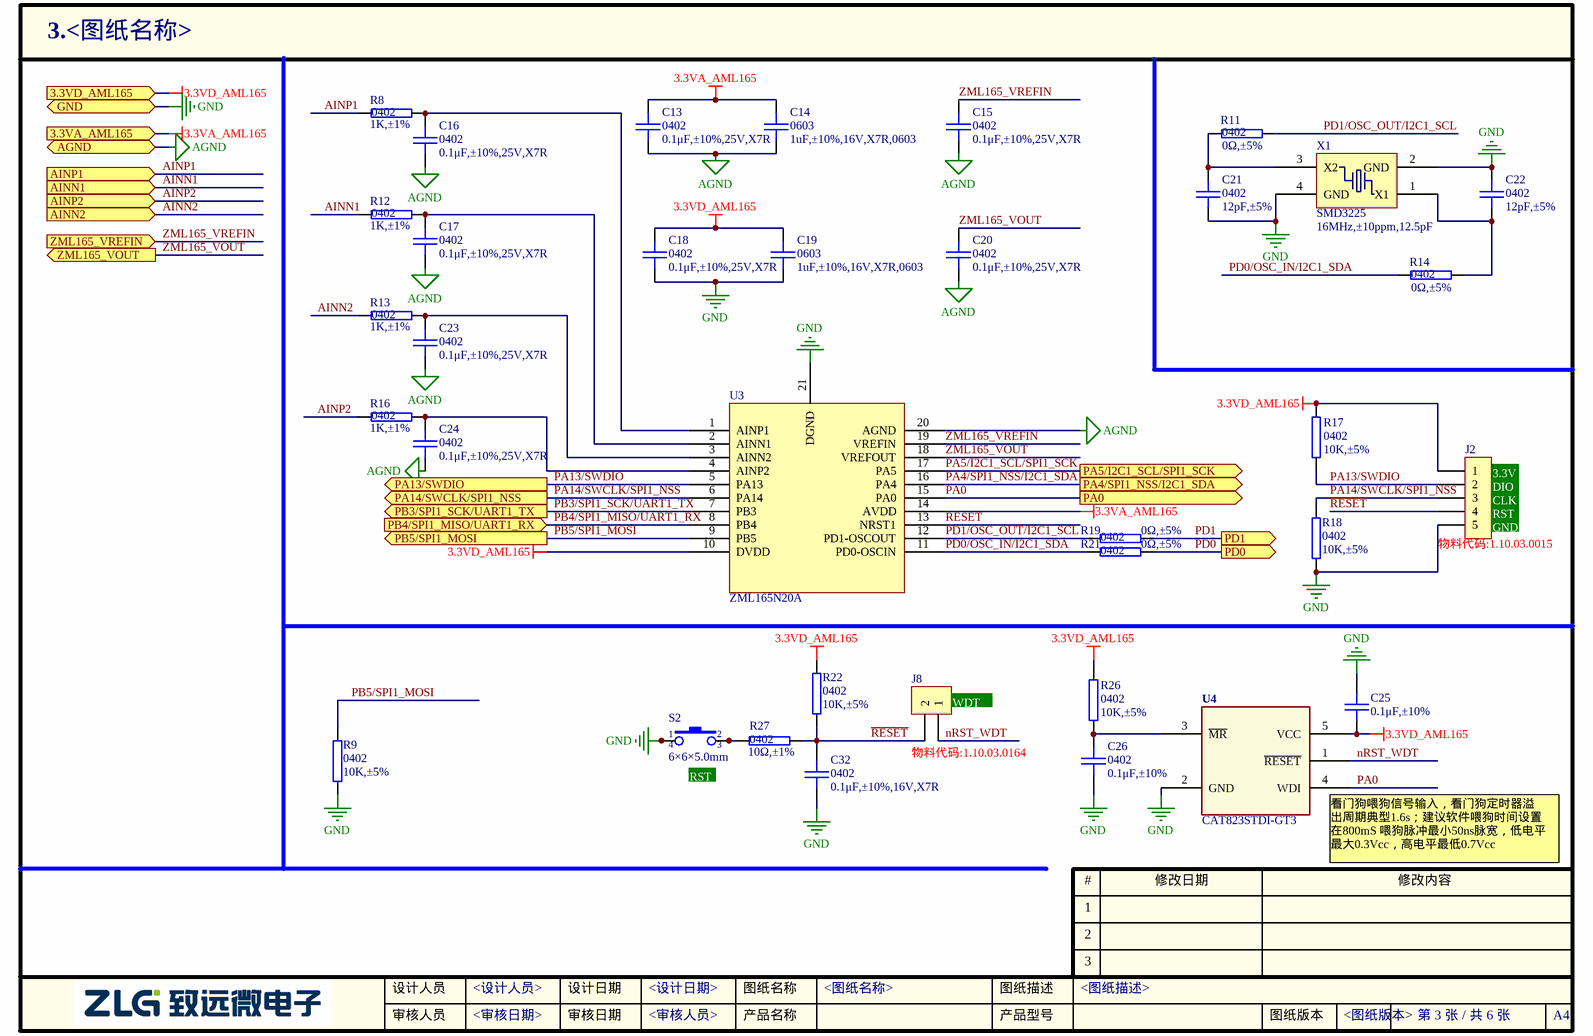
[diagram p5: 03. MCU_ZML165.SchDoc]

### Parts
C13  封装: 0402  型号: 0.1μF,±10%,25V,X7R  [0402C]  (hidden comment: 0.1μF)
C14  封装: 0603  型号: 1uF,±10%,16V,X7R,0603  [0603C]  (hidden comment: 16V,TDK,1uF)
C15  封装: 0402  型号: 0.1μF,±10%,25V,X7R  [0402C]  (hidden comment: 0.1μF)
C16  封装: 0402  型号: 0.1μF,±10%,25V,X7R  [0402C]  (hidden comment: GCM155R71E104KE02D,0.1μF)
C17  封装: 0402  型号: 0.1μF,±10%,25V,X7R  [0402C]  (hidden comment: GCM155R71E104KE02D,0.1μF)
C18  封装: 0402  型号: 0.1μF,±10%,25V,X7R  [0402C]  (hidden comment: 0.1μF)
C19  封装: 0603  型号: 1uF,±10%,16V,X7R,0603  [0603C]  (hidden comment: 16V,TDK,1uF)
C20  封装: 0402  型号: 0.1μF,±10%,25V,X7R  [0402C]  (hidden comment: 0.1μF)
C21  封装: 0402  [0402C]  (hidden comment: 12pF,±5%)
C22  封装: 0402  [0402C]  (hidden comment: 12pF,±5%)
C23  封装: 0402  型号: 0.1μF,±10%,25V,X7R  [0402C]  (hidden comment: GCM155R71E104KE02D,0.1μF)
C24  封装: 0402  型号: 0.1μF,±10%,25V,X7R  [0402C]  (hidden comment: GCM155R71E104KE02D,0.1μF)
C25  0.1μF,±10%  [0402C]
C26  封装: 0402  [0402C]  (hidden comment: 0.1μF,±10%)
C32  封装: 0402  型号: 0.1μF,±10%,16V,X7R  [0402C]  (hidden comment: 0.1μF,±10%)
J2  (no value)  [SIP-5-2.54-6.0-R90]
J8  (no value)  [SIP-2-2.54]
R8  封装: 0402  [0402R]  (hidden comment: 1K,±1%)
R9  封装: 0402  型号: 10K,±5%  [0402R]  (hidden comment: RTT02103JTH,10K)
R11  封装: 0402  型号: 0Ω,±5%  [0402R]  (hidden comment: RTT02000JTH,0Ω)
R12  封装: 0402  [0402R]  (hidden comment: 1K,±1%)
R13  封装: 0402  [0402R]  (hidden comment: 1K,±1%)
R14  封装: 0402  型号: 0Ω,±5%  [0402R]  (hidden comment: RTT02000JTH,0Ω)
R16  封装: 0402  [0402R]  (hidden comment: 1K,±1%)
R17  封装: 0402  型号: 10K,±5%  [0402R]  (hidden comment: RTT02103JTH,10K)
R18  封装: 0402  型号: 10K,±5%  [0402R]  (hidden comment: RTT02103JTH,10K)
R19  封装: 0402  型号: 0Ω,±5%  [0402R]  (hidden comment: RTT02000JTH,0Ω)
R21  封装: 0402  型号: 0Ω,±5%  [0402R]  (hidden comment: RTT02000JTH,0Ω)
R22  封装: 0402  型号: 10K,±5%  [0402R]  (hidden comment: RTT02103JTH,10K)
R26  封装: 0402  型号: 10K,±5%  [0402R]  (hidden comment: RTT02103JTH,10K)
R27  封装: 0402  [0402R]  (hidden comment: 10Ω,±1%)
S2  6×6×5.0mm  [KEY-6S]
U3  ZML165N20A  [QFN50P400X400X85-21N]
U4  CAT823STDI-GT3  [SOT-23-5]
X1  封装: SMD3225  型号: 16MHz,±10ppm,12.5pF  [OSCCC250X320X80-4N]  (hidden comment: JYD3A1C7G5-12.5-16.000,16.0000MHz)

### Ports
3.3VA_AML165 (in), 3.3VD_AML165 (in), AGND (bidir), AINN1 (in), AINN2 (in), AINP1 (in), AINP2 (in), GND (bidir), PA0 (out), PA4/SPI1_NSS/I2C1_SDA (out), PA5/I2C1_SCL/SPI1_SCK (out), PA13/SWDIO (out), PA14/SWCLK/SPI1_NSS (out), PB3/SPI1_SCK/UART1_TX (out), PB4/SPI1_MISO/UART1_RX (in), PB5/SPI1_MOSI (out), PD0 (out), PD1 (out), ZML165_VOUT (out), ZML165_VREFIN (in)

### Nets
3.3VA_AML165: C13.2 C14.2 U3.14(AVDD) ; port 3.3VA_AML165  [project net 3.3VA]
3.3VD_AML165: C18.2 C19.2 C25.2 J2.1 R17.1 R22.2 R26.2 U3.10(DVDD) U4.5(VCC) ; port 3.3VD_AML165  [project net 3.3V]
AGND: C13.1 C14.1 C15.1 C16.1 C17.1 C20.1 C23.1 C24.1 U3.20(AGND) ; port AGND
GND: C18.1 C19.1 C21.2 C22.1 C25.1 C26.1 C32.2 J2.5 R9.1 R18.2 S2.1 S2.4 U3.21(DGND) U4.2(GND) X1.2(GND) X1.4(GND) ; port GND
AINN1: R12.1 ; port AINN1
AINN2: R13.1 ; port AINN2
AINP1: R8.1 ; port AINP1
AINP2: R16.1 ; port AINP2
nRST_WDT: J8.1 U4.1(~{RESET})
PA0: U3.15(PA0) U4.4(WDI) ; port PA0  [project net MicroPort_ADC1]
PA4/SPI1_NSS/I2C1_SDA: U3.16(PA4) ; port PA4/SPI1_NSS/I2C1_SDA  [project net LM75_SDA]
PA5/I2C1_SCL/SPI1_SCK: U3.17(PA5) ; port PA5/I2C1_SCL/SPI1_SCK  [project net LM75_SCL]
PA13/SWDIO: J2.2 R17.2 U3.5(PA13) ; port PA13/SWDIO  [project net GPIO_KEY]
PA14/SWCLK/SPI1_NSS: J2.3 R18.1 U3.6(PA14) ; port PA14/SWCLK/SPI1_NSS  [project net MicroPort_CS]
PB3/SPI1_SCK/UART1_TX: U3.7(PB3) ; port PB3/SPI1_SCK/UART1_TX  [project net GPIO_LED1]
PB4/SPI1_MISO/UART1_RX: U3.8(PB4) ; port PB4/SPI1_MISO/UART1_RX  [project net GPIO_LED0]
PB5/SPI1_MOSI: R9.2 U3.9(PB5) ; port PB5/SPI1_MOSI  [project net MicroPort_MOSI]
PD0: R21.1 ; port PD0  [project net MicroPort_I/O2]
PD0/OSC_IN/I2C1_SDA: R14.2 R21.2 U3.11(PD0-OSCIN)
PD1: R19.1 ; port PD1  [project net MicroPort_I/O3]
PD1/OSC_OUT/I2C1_SCL: R11.1 R19.2 U3.12(PD1-OSCOUT)
~{RESET}: C32.1 J2.4 J8.2 R22.1 R27.2 U3.13(NRST1)
ZML165_VOUT: C20.2 U3.18(VREFOUT) ; port ZML165_VOUT  [project net VREFOUT]
ZML165_VREFIN: C15.2 U3.19(VREFIN) ; port ZML165_VREFIN  [project net REF_ADC]
NetC16_2: C16.2 R8.2 U3.1(AINP1)
NetC17_2: C17.2 R12.2 U3.2(AINN1)
NetC21_1: C21.1 R11.2 X1.3(X2)
NetC22_2: C22.2 R14.1 X1.1(X1)
NetC23_2: C23.2 R13.2 U3.3(AINN2)
NetC24_2: C24.2 R16.2 U3.4(AINP2)
NetC26_2: C26.2 R26.1 U4.3(~{MR})
NetR27_1: R27.1 S2.2 S2.3

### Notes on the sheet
- (near J2) 3.3V
- (near J2) DIO
- (near J2) CLK
- (near J2) RST
- (near J2) 物料代码:1.10.03.0015
- (near J2) GND
- (near J8) WDT
- RST
- (near J8) 物料代码:1.10.03.0164
- (near U4) 看门狗喂狗信号输入，看门狗定时器溢
  出周期典型1.6s；建议软件喂狗时间设置
  在800mS 喂狗脉冲最小50ns脉宽，低电平
  最大0.3Vcc，高电平最低0.7Vcc

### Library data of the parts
C13 C15-C18 C20 C23 C24 = 1.02.17.0118: as C30 on sheet 04. Analog
C14 C19 = 02.01.00365: CGA3E1X7R1C105KT0Y0N,1uF,±10%,16V,X7R,0603,TDK,; 旧物料代码: 1.02.01.0091; 名称: 电容; 贴片和直插: SMT; PCB备注: 180312ZW; 器件优选方案: 推荐使用
C21 C22 = 1.02.17.0018: GRM1555C1H120JA01D,12pF,±5%,50V,C0G,0402,muRata,RoHS; 名称: 电容; 设备封装名称: C0402_12PF_COG_50V_5%; 贴片和直插: SMT; 器件优选方案: 正常状态，可以选用
C25 = 1.02.17.0006: GRM155R71C104KA88D,0.1μF,±10%,16V,X7R,0402,muRata,RoHS; 名称: 电容; 封装: 0402; 设备封装名称: C0402_0.1uF_X7R_16V_10%; 贴片和直插: SMT; 器件优选方案: 正常状态，可以选用
C26 C32 = 1.02.17.0006: GRM155R71C104KA88D,0.1μF,±10%,16V,X7R,0402,muRata,RoHS; 名称: 电容; 设备封装名称: C0402_0.1uF_X7R_16V_10%; 贴片和直插: SMT; 器件优选方案: 正常状态，可以选用
J2 = CON5: Connector; 物料代码: 1.10.03.0015
J8 = CON2: Connector; 物料代码: 1.10.03.0164
R8 R12 R13 R16 = 1.01.17.0016: as R43 on sheet 04. Analog
R9 R17 R18 R22 R26 = 1.01.17.0006: RTT02103JTH,10K,±5%,0402,RALEC,RoHS; 名称: 电阻; 设备封装名称: R0402_10K; 贴片和直插: SMT; 器件优选方案: 正常状态，可以选用
R11 R14 R19 R21 = 1.01.17.0004: RTT02000JTH,0Ω,±5%,0402,RALEC,RoHS; 名称: 电阻; 设备封装名称: R0402_0R; 贴片和直插: SMT; 器件优选方案: 正常状态，可以选用
R27 = 1.01.17.0059: 10Ω,±1%,1/16W,0402,RoHS; 名称: 电阻; 设备封装名称: R0402_10R_1%; 厂商: Ralec; 贴片和直插: SMT; 器件优选方案: 正常状态，可以选用
S2 = 1.09.01.0003: TS0641-0501B,6×6×5.0mm,黑色,SMD,卷带装,RoHS; 名称: 轻触开关; 贴片和直插: SMT; 器件优选方案: 正常状态，可以选用
U3 = 89.12.00028: 名称: 集成电路; 厂商: ZHIYUAN; 贴片和直插: SMT; PCB备注: 200721hcj
U4 = CAT823: 1.05.07.0025
X1 = 1.07.03.0077: JYD3A1C7G5-12.5-16.000,16.0000MHz,±10ppm,12.5pF,-40~85℃,SMD3225,JYEG,RoHS; 名称: 晶体; 贴片和直插: SMT; PCB备注: 151225lmd171128ZW; 器件优选方案: 正常状态，可以选用

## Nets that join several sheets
3.3V: 02. PWR_ZL6205 (5 pins), 05. Peripherals (9 pins), 06. Mini-Micro_Port (J4.1 J27.26), 03. MCU_ZML165 (9 pins)
3.3VA: 04. Analog (7 pins), 02. PWR_ZL6205 (L2.2 T3.1), 06. Mini-Micro_Port (J19.3), 03. MCU_ZML165 (C13.2 C14.2 U3.14)
5V: 02. PWR_ZL6205 (7 pins), 05. Peripherals (R40.1), 06. Mini-Micro_Port (J4.2 J19.1)
AGND: 04. Analog (22 pins), 02. PWR_ZL6205 (11 pins), 03. MCU_ZML165 (9 pins)
EARTH1: 01. MAIN (C43.2 HOLE1.1 R42.2), 02. PWR_ZL6205 (6 pins)
GND: 01. MAIN (C43.1 R42.1), 02. PWR_ZL6205 (14 pins), 05. Peripherals (9 pins), 06. Mini-Micro_Port (J4.3 J4.4 J27.1 J27.18), 03. MCU_ZML165 (16 pins)
AINN1: 04. Analog (J12.2 J15.2 J25.3), 03. MCU_ZML165 (R12.1)
AINN2: 04. Analog (J18.2), 03. MCU_ZML165 (R13.1)
AINP1: 04. Analog (J5.2 J15.1 J25.1 J25.5), 03. MCU_ZML165 (R8.1)
AINP2: 04. Analog (J17.2), 03. MCU_ZML165 (R16.1)
GPIO_KEY: 05. Peripherals (J14.1 R41.1), 06. Mini-Micro_Port (J4.20 J27.3), 03. MCU_ZML165 (J2.2 R17.2 U3.5)
GPIO_LED0: 05. Peripherals (J9.1), 06. Mini-Micro_Port (J4.9 J4.10 J27.9 J27.20), 03. MCU_ZML165 (U3.8)
GPIO_LED1: 05. Peripherals (J10.1), 06. Mini-Micro_Port (J4.12 J4.13 J27.8 J27.19), 03. MCU_ZML165 (U3.7)
LM75_SCL: 05. Peripherals (J11.1), 06. Mini-Micro_Port (J4.17 J27.12), 03. MCU_ZML165 (U3.17)
LM75_SDA: 05. Peripherals (J13.1), 06. Mini-Micro_Port (J4.19 J27.13), 03. MCU_ZML165 (U3.16)
MicroPort_ADC1: 05. Peripherals (J7.1), 06. Mini-Micro_Port (J4.18 J27.16), 03. MCU_ZML165 (U3.15 U4.4)
MicroPort_CS: 06. Mini-Micro_Port (J4.7 J27.22), 03. MCU_ZML165 (J2.3 R18.1 U3.6)
MicroPort_I/O2: 06. Mini-Micro_Port (J4.14 J27.11), 03. MCU_ZML165 (R21.1)
MicroPort_I/O3: 06. Mini-Micro_Port (J4.16 J27.10), 03. MCU_ZML165 (R19.1)
MicroPort_MOSI: 06. Mini-Micro_Port (J4.15 J27.21), 03. MCU_ZML165 (R9.2 U3.9)
REF_ADC: 04. Analog (J20.2), 03. MCU_ZML165 (C15.2 U3.19)
VREFOUT: 04. Analog (C33.2 J16.2), 03. MCU_ZML165 (C20.2 U3.18)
